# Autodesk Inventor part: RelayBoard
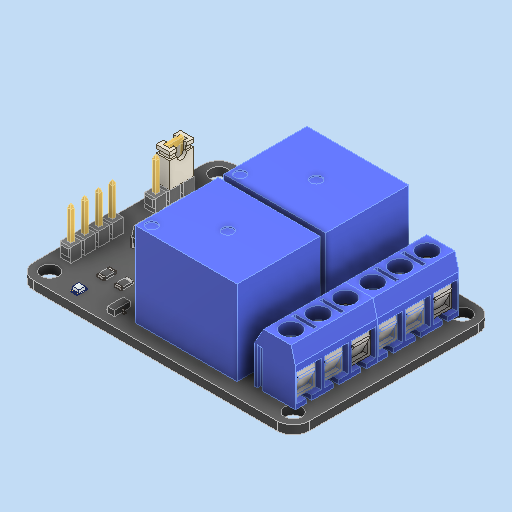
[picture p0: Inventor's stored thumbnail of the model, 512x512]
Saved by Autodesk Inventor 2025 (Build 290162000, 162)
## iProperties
Created: 2016-02
Part Number: RelayBoard
Material: Generico
Description: STEP AP214
Document SubType Name: Modeling
Designer: Ryzen5700u
Density: 1 g/cm^3
Appearance: Default
Title: RelayBoard.STEP
Sending System: SolidWorks 2015
Preprocessor: SwSTEP 2.0
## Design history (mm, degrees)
feature "RelayBase_1:1"
feature "Terminator_2:1"
feature "Terminator_2:2"
feature "Terminator_2:3"
feature "Terminator_2:4"
feature "Terminator_2:5"
feature "Terminator_2:6"
feature "Terminator_2:7"
feature "Terminator_2:8"
feature "Terminator_2:9"
feature "Terminator_2:10"
feature "Terminator_3:1"
feature "Terminator_3:2"
feature "Terminator_3:3"
feature "Terminator_3:4"
feature "Terminator_3:5"
feature "Terminator_3:6"
feature "Terminator_3:7"
feature "Terminator_3:8"
feature "Terminator_3:9"
feature "Terminator_3:10"
feature "D1_4:1"
feature "sot-23-j3y_5:1"
feature "sot-23-j3y_5:2"
feature "Jumper_6:1"
feature "Jumper_6:2"
feature "PC-817_7:1"
feature "PC-817_7:2"
feature "PC-817_7:3"
feature "Relay_8:1"
feature "smdres_102_9:1"
feature "smdres_102_9:2"
feature "smdres_102_9:3"
feature "smdres_115_10:1"
feature "smdres_115_10:2"
feature "smdres_115_10:3"
feature "BreakAwayHeaders_3PinShort_11:1"
feature "BreakAwayHeaders_3PinShort_11:2"
feature "BreakAwayHeaders_3PinShort_11:3"
feature "BreakAwayHeaders_3PinShort_11:4"
feature "BreakAwayHeaders_3PinShort_11:5"
feature "BreakAwayHeaders_3PinShort_11:6"
feature "BreakAwayHeaders_4PinShort_12:1"
feature "BreakAwayHeaders_4PinShort_12:2"
feature "BreakAwayHeaders_4PinShort_12:3"
feature "BreakAwayHeaders_4PinShort_12:4"
feature "BreakAwayHeaders_4PinShort_12:5"
feature "BreakAwayHeaders_4PinShort_12:6"
feature "BreakAwayHeaders_4PinShort_12:7"
feature "BreakAwayHeaders_4PinShort_12:8"
feature "smallled_SmallRelay_13:1"
feature "smallled_SmallRelay_13:2"
feature "smallled_SmallRelay_13:3"
feature "smallled_SmallRelay_13:4"
feature "Relay_14:1"
feature "D1_15:1"
feature "sot-23-j3y_16:1"
feature "sot-23-j3y_16:2"
feature "PC-817_17:1"
feature "PC-817_17:2"
feature "PC-817_17:3"
feature "smallled_SmallRelay_18:1"
feature "smallled_SmallRelay_18:2"
feature "smallled_SmallRelay_18:3"
feature "smallled_SmallRelay_18:4"
feature "smdres_102_19:1"
feature "smdres_102_19:2"
feature "smdres_102_19:3"
feature "smdres_115_20:1"
feature "smdres_115_20:2"
feature "smdres_115_20:3"
node "Solido1"
node "Solido2"
node "Solido3"
node "Solido4"
node "Solido5"
node "Solido6"
node "Solido7"
node "Solido8"
node "Solido9"
node "Solido10"
node "Solido11"
node "Solido12"
node "Solido13"
node "Solido14"
node "Solido15"
node "Solido16"
node "Solido17"
node "Solido18"
node "Solido19"
node "Solido20"
node "Solido21"
node "Solido22"
node "Solido23"
node "Solido24"
node "Solido25"
node "Solido26"
node "Solido27"
node "Solido28"
node "Solido29"
node "Solido30"
node "Solido31"
node "Solido32"
node "Solido33"
node "Solido34"
node "Solido35"
node "Solido36"
node "Solido37"
node "Solido38"
node "Solido39"
node "Solido40"
node "Solido41"
node "Solido42"
node "Solido43"
node "Solido44"
node "Solido45"
node "Solido46"
node "Solido47"
node "Solido48"
node "Solido49"
node "Solido50"
node "Solido51"
node "Solido52"
node "Solido53"
node "Solido54"
node "Solido55"
node "Solido56"
node "Solido57"
node "Solido58"
node "Solido59"
node "Solido60"
node "Solido61"
node "Solido62"
node "Solido63"
node "Solido64"
node "Solido65"
node "Solido66"
node "Solido67"
node "Solido68"
node "Solido69"
node "Solido70"
node "Solido71"
